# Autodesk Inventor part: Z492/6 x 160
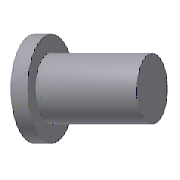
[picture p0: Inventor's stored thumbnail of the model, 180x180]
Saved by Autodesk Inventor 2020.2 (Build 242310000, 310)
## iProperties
Manager: www.cadconsulting.pl
Company: Fabian Stasiak CAD Consulting
Created: 2014-02
Part Number: Z492/6 x 160
Material: Special copper alloy, berylliumfree
Description: Core Pin
Document SubType Name: Modeling
Standard: ISO
Designer: F.Stasiak
Standard Revision: 1
Manufacturer: HASCO
Language: pl-PL
Size Designation: -6 x 160
Categories: <MemberInstance><Categories><Category DisplayName="Forma wtryskowa" InternalName="349578f2-f4d4-4954-8c09-8e99297a61c0" Mnemonic="MOLD"><Category DisplayName="W
Mass: 5.34093 g
Surface Area: 25.2527 cm^2
Volume: 5.34093 cm^3
Density: 8.4 g/cm^3
Appearance: Aluminium - ciemne
Catalog Web Link: www.expertbooks.pl
IsCustomPart: 1
Author: F.Stasiak
Subject: Zbiór ćwiczeń. Autodesk Inventor 2020. Kurs Professional
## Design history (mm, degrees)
sketch "Sketch1"
  geometry: L1 (0, 0)-(6, 0); L2 (6, 0)-(6, 5); L3 (6, 5)-(3, 5); L4 (3, 5)-(3, 160); L5 (3, 160)-(0, 160); L6 (0, 0)-(0, 160); L7 (0, 96)-(0, -16) reference; 1 further point
  constraints: 12 end point, 3 parallel, 2 perpendicular, 1 coincident
  dimensions: "d5" = 5 distance between parallel lines of L1 L3 (= k); "d28" = 160 distance between parallel lines of L5 L1 (= l1); "d44" = 6 diameter of L4 L7 (= d1); "d45" = 12 diameter of L2 L7 (= d2)
revolve "Revolution1" sketch "Sketch1" stored, may be unused: angle "d7" = 90 deg
fillet "Fillet1" dims "d27" = 0.5 (= R)
workplane "Work Plane1"
sketch "Sketch2"
  geometry: 2 further points
  constraints: 1 vertical alignment
  dimensions: "d31" = 2.5 distance of point (0, -2.5) point (0, 0) (= 0.5 x k)
hole "Anti_Rotary Hole" sketch "Sketch2" at (0, 0) diameter "d32" = 1.05 (= Anti_Rotary_D); stored, may be unused: countersink angle "d36" = 90 deg, drill point angle "d38" = 118 deg; dims "d33" = 6, "d34" = 4, "d35" = 2, "d37" = 1.575 (= 1.5 x Anti_Rotary_D)
sketch "Sketch3"
  geometry: L1 (-3.3, 5.011)-(-3.3, -5.011); A1 r 6 centre (0, 0) between (-3.3, 5.011) and (-3.3, -5.011) reference; 1 further point
  constraints: 2 end point, 2 point on circle, 1 vertical
  dimensions: "d39" = 3.3 distance from line of point (0, 0) L1 (= Anti_Rotary_P)
extrude "Anti_Rotary Plane" cut sketch "Sketch3" extent not by distance; stored distance "d40" = 5.3 (computed from k); taper "d41" = 0 deg
body "Solid1"
other parameters: "d1" = 6 [user parameter; used in 1 equation term], "d2" = 12 [user parameter; used in 1 equation term], "k" = 5 [user parameter; used in 3 equation terms], "l1" = 160 [user parameter; used in 1 equation term], "d20" = 0, "d21" = 0, "R" = 0.5 [user parameter; used in 1 equation term], "d29" = 0, "d30" = 0, "Anti_Rotary_P" = 3.3 [user parameter; used in 1 equation term], "Anti_Rotary_D" = 1.05 [user parameter; used in 2 equation terms], "d42" = 0, "d43" = 0, "IsARPlane" = 0 [user parameter], "IsARHole" = 0 [user parameter]
